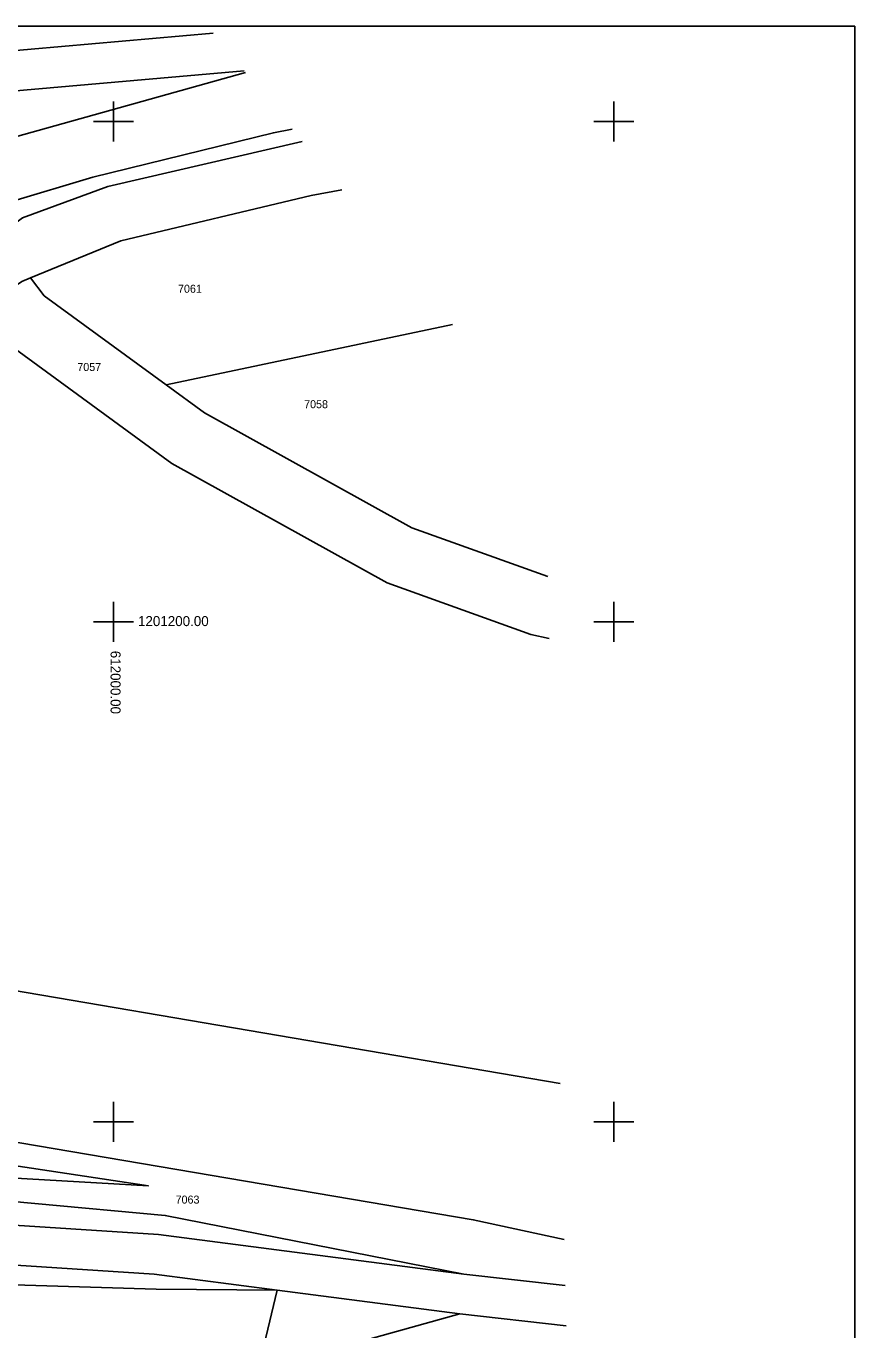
# Model space of a CAD drawing. Extents: x -612546 to -611926, y -1201932 to -1200444.
# Drawn here: x -612008.7 to -611925.9, y -1201270.8 to -1201140.5 of the extents above; entities that cross this region are included whole.
import ezdxf

# ---------------------------------------------------------------- set-up
doc = ezdxf.new("R2010")
doc.units = 0
for name, color, linetype in [('61 legenda křížky', 7, 'Continuous'), ('Hranice parcel', 7, 'Continuous'), ('Parcelní čísla', 7, 'Continuous'), ('Vnitřní kresba', 7, 'Continuous'), ('Vrstva 63', 7, 'Continuous')]:
    doc.layers.add(name, color=color, linetype=linetype)

msp = doc.modelspace()

# ---------------------------------------------------------------- linework, layer by layer
at = {"layer": '61 legenda křížky'}
for p, q in [((-612000, -1201152), (-612000, -1201148)), ((-611950, -1201152), (-611950, -1201148)), ((-612002, -1201150), (-611998, -1201150)), ((-611952, -1201150), (-611948, -1201150)), ((-612000, -1201202), (-612000, -1201198)), ((-611950, -1201202), (-611950, -1201198)), ((-612002, -1201200), (-611998, -1201200)), ((-611952, -1201200), (-611948, -1201200)), ((-612000, -1201252), (-612000, -1201248)), ((-611950, -1201252), (-611950, -1201248)), ((-612002, -1201250), (-611998, -1201250)), ((-611952, -1201250), (-611948, -1201250))]:
    msp.add_line(p, q, dxfattribs=at)
at = {"layer": 'Hranice parcel'}
for p, q in [((-612021.69, -1201234.86), (-611955.36, -1201246.17)), ((-611983.63, -1201266.82), (-611965.41, -1201269.18))]:
    msp.add_line(p, q, dxfattribs=at)
for points in [[(-612027.25, -1201146.78), (-612011.25, -1201143.03), (-611990.03, -1201141.17)], [(-611986.82, -1201145.08), (-612009.79, -1201151.53), (-612016.33, -1201156.17), (-612020.4, -1201159.05)], [(-611977.19, -1201156.81), (-611980.24, -1201157.4), (-611999.25, -1201161.93), (-612008.29, -1201165.62)], [(-612008.29, -1201165.62), (-612009.17, -1201165.98), (-612012.62, -1201168.3), (-612013.17, -1201169.11)], [(-611994.74, -1201176.31), (-612006.91, -1201167.41), (-612008.29, -1201165.62)], [(-612013.17, -1201169.11), (-612011.15, -1201171.75), (-611994.16, -1201184.17), (-611972.66, -1201196.1), (-611958.29, -1201201.26), (-611956.46, -1201201.67)], [(-611966.12, -1201170.3), (-611994.74, -1201176.31)], [(-611956.61, -1201195.49), (-611970.18, -1201190.62), (-611990.92, -1201179.11), (-611994.74, -1201176.31)], [(-611954.97, -1201261.74), (-611964.06, -1201259.77), (-612032.15, -1201248.22), (-612039.89, -1201246.1)], [(-611954.86, -1201266.33), (-611964.99, -1201265.2), (-611994.82, -1201259.34), (-612020.92, -1201256.96), (-612032.02, -1201256.62), (-612039.62, -1201257.09)], [(-612038.38, -1201265.42), (-611995.74, -1201266.7), (-611983.63, -1201266.82)], [(-611983.63, -1201266.82), (-611995.73, -1201317.36), (-611989.14, -1201396.64)], [(-611965.41, -1201269.18), (-611978.05, -1201272.7), (-611982.14, -1201277.79), (-611991.69, -1201317.67), (-611985.19, -1201395.99), (-611964.05, -1201475.97)], [(-611965.41, -1201269.18), (-611954.76, -1201270.37)]]:
    msp.add_lwpolyline(points, dxfattribs=at)
at = {"layer": 'Vnitřní kresba'}
for points in [[(-612014.66, -1201148.75), (-612010.9, -1201147.01), (-611986.95, -1201144.92)], [(-612013.47, -1201160.38), (-612010.29, -1201158.03), (-612002.05, -1201155.54), (-611984.02, -1201151.11), (-611982.15, -1201150.76)], [(-612012.24, -1201161.99), (-612009.09, -1201159.63), (-612000.56, -1201156.48), (-611981.14, -1201151.99)], [(-612040.03, -1201249.7), (-612022.34, -1201252.49), (-611996.5, -1201256.4), (-612032.89, -1201254.3), (-612039.97, -1201254.67)], [(-612039.25, -1201259.57), (-612020.79, -1201259.6), (-611995.5, -1201261.25), (-611964.99, -1201265.2)], [(-612038.66, -1201263.56), (-612021.05, -1201263.59), (-611995.94, -1201265.23), (-611983.63, -1201266.82)]]:
    msp.add_lwpolyline(points, dxfattribs=at)
at = {"layer": 'Vrstva 63'}
for p, q in [((-612222.92, -1201140.45), (-611925.92, -1201140.45)), ((-611925.92, -1201140.45), (-611925.92, -1201560.45))]:
    msp.add_line(p, q, dxfattribs=at)

# ---------------------------------------------------------------- texts
at = {"layer": '61 legenda křížky'}
msp.add_text('1201200.00', height=1, dxfattribs=at).set_placement((-611997.55, -1201200.43))
msp.add_text('612000.00', height=1, rotation=270, dxfattribs=at).set_placement((-612000.29, -1201202.9))
at = {"layer": 'Parcelní čísla'}
for s, p in [('7061', (-611993.55, -1201167.11)), ('7057', (-612003.61, -1201174.93)), ('7058', (-611980.95, -1201178.65)), ('7063', (-611993.79, -1201258.16))]:
    msp.add_text(s, height=0.8, dxfattribs=at).set_placement(p)

doc.saveas('drawing.dxf')
